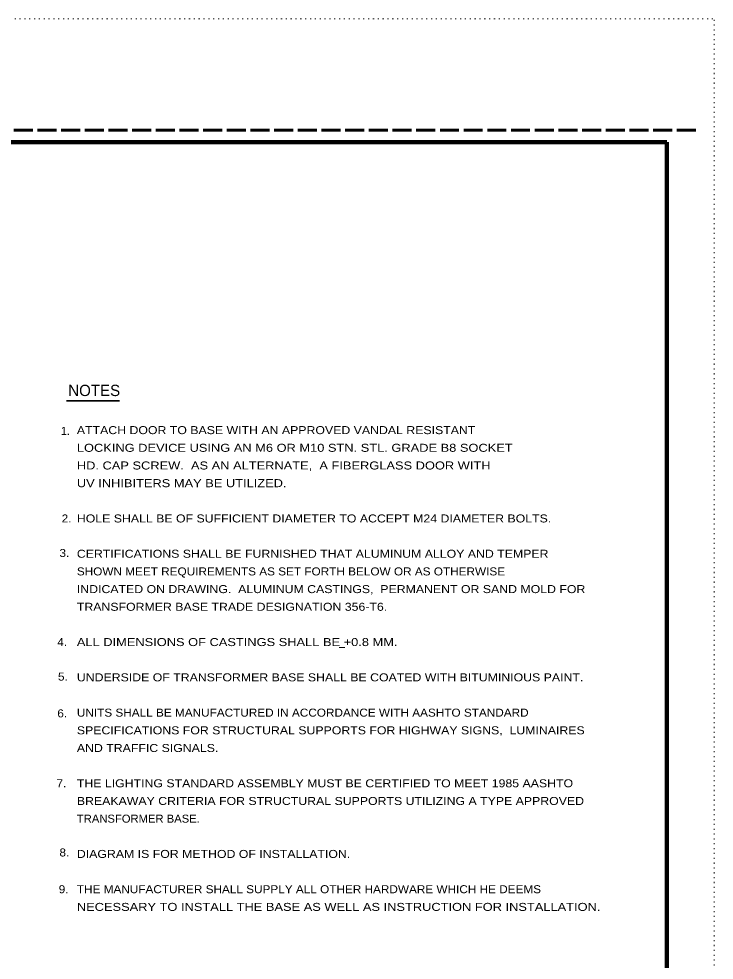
# Model space of a CAD drawing. Extents: x 312583 to 312854, y 144419 to 144597.
# Drawn here: x 312787.4 to 312853.5, y 144507.4 to 144596.8 of the extents above; entities that cross this region are included whole.
import ezdxf
from ezdxf.enums import TextEntityAlignment as Align

# ---------------------------------------------------------------- set-up
doc = ezdxf.new("R2010")
doc.units = 0
doc.header["$LTSCALE"] = 0.3
doc.linetypes.add('DOTTED', pattern=[1.5, 0.3, -1.2])
doc.linetypes.add('LONG_DASHED', pattern=[7.5, 6, -1.5])
for name, color, linetype, lineweight in [('1', 7, 'Continuous', 40), ('2', 7, 'Continuous', 13), ('62', 7, 'DOTTED', 13), ('63', 7, 'LONG_DASHED', 60)]:
    doc.layers.add(name, color=color, linetype=linetype, lineweight=lineweight)

msp = doc.modelspace()

# ---------------------------------------------------------------- linework, layer by layer
at = {"layer": '1', "lineweight": 158}
msp.add_line((312849, 144423.1446), (312849, 144585.0846), dxfattribs=at)
msp.add_lwpolyline([(312616.5, 144423.1446), (312616.5, 144585.0846), (312849, 144585.0846)], dxfattribs=at)
at = {"layer": '2', "lineweight": 35}
msp.add_line((312791.975, 144560.5034), (312797.0148, 144560.5034), dxfattribs=at)
at = {"layer": '2'}
msp.add_line((312817.866, 144537.1054), (312818.3975, 144537.1054), dxfattribs=at)
at = {"layer": '62'}
msp.add_line((312601.2, 144596.7846), (312853.5, 144596.7846), dxfattribs=at)
msp.add_lwpolyline([(312601.2, 144418.5846), (312853.5, 144418.5846), (312853.5, 144596.7846)], dxfattribs=at)
at = {"layer": '63'}
msp.add_line((312851.75, 144586.2246), (312583.526, 144586.2246), dxfattribs=at)

# ---------------------------------------------------------------- texts
at = {"layer": '2'}
msp.add_text('NOTES', height=1.07, dxfattribs=at).set_placement((312794.5952, 144560.9655), align=Align.CENTER)
msp.add_text('1.  ', height=0.76, dxfattribs=at).set_placement((312791.4321, 144557.2812))
for s, width, p in [('ATTACH DOOR TO BASE WITH AN APPROVED VANDAL RESISTANT', 1.15, (312792.9486, 144557.3514)), ('LOCKING DEVICE USING AN M6 OR M10 STN. STL. GRADE B8 SOCKET', 1.2, (312792.9486, 144555.6724)), ('HD. CAP SCREW.  AS AN ALTERNATE,  A FIBERGLASS DOOR WITH', 1.2, (312792.9486, 144553.9934)), ('UV INHIBITERS MAY BE UTILIZED.', 1.2, (312792.9486, 144552.3144)), ('2.  ', 1.1, (312791.505, 144548.9639)), ('HOLE SHALL BE OF SUFFICIENT DIAMETER TO ACCEPT M24 DIAMETER BOLTS.', 1.15, (312792.9486, 144548.964)), ('3.  ', 1.1, (312791.2949, 144545.6839)), ('CERTIFICATIONS SHALL BE FURNISHED THAT ALUMINUM ALLOY AND TEMPER', 1.15, (312792.9486, 144545.6137)), ('SHOWN MEET REQUIREMENTS AS SET FORTH BELOW OR AS OTHERWISE', 1.1, (312792.9486, 144543.9347)), ('INDICATED ON DRAWING.  ALUMINUM CASTINGS,  PERMANENT OR SAND MOLD FOR', 1.15, (312792.9486, 144542.2557)), ('TRANSFORMER BASE TRADE DESIGNATION 356-T6.', 1.15, (312792.9486, 144540.5767)), ('4.  ', 1.1, (312791.0847, 144537.2265)), ('ALL DIMENSIONS OF CASTINGS SHALL BE +0.8 MM.', 1.2, (312792.9486, 144537.2264)), ('5.  ', 1.1, (312791.1547, 144533.9462)), ('UNDERSIDE OF TRANSFORMER BASE SHALL BE COATED WITH BITUMINIOUS PAINT.', 1.15, (312792.9486, 144533.876)), ('6.  ', 1.1, (312791.0896, 144530.4556)), ('UNITS SHALL BE MANUFACTURED IN ACCORDANCE WITH AASHTO STANDARD', 1.1, (312792.9486, 144530.5257)), ('SPECIFICATIONS FOR STRUCTURAL SUPPORTS FOR HIGHWAY SIGNS,  LUMINAIRES', 1.15, (312792.9486, 144528.8467)), ('AND TRAFFIC SIGNALS.', 1.15, (312792.9486, 144527.1677)), ('7.  ', 1.1, (312791.0146, 144523.8173)), ('THE LIGHTING STANDARD ASSEMBLY MUST BE CERTIFIED TO MEET 1985 AASHTO', 1.15, (312792.9486, 144523.8174)), ('BREAKAWAY CRITERIA FOR STRUCTURAL SUPPORTS UTILIZING A TYPE APPROVED', 1.15, (312792.9486, 144522.1384)), ('TRANSFORMER BASE.', 1.05, (312792.9486, 144520.4594)), ('8.  ', 1.1, (312791.2948, 144517.2493)), ('DIAGRAM IS FOR METHOD OF INSTALLATION.', 1.15, (312792.9486, 144517.109)), ('9.  ', 1.1, (312791.2248, 144513.7587)), ('THE MANUFACTURER SHALL SUPPLY ALL OTHER HARDWARE WHICH HE DEEMS', 1.1, (312792.9486, 144513.7587)), ('NECESSARY TO INSTALL THE BASE AS WELL AS INSTRUCTION FOR INSTALLATION.', 1.2, (312792.9486, 144512.0797))]:
    msp.add_text(s, height=0.76, dxfattribs=dict(at, width=width)).set_placement(p)

doc.saveas('drawing.dxf')
